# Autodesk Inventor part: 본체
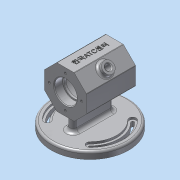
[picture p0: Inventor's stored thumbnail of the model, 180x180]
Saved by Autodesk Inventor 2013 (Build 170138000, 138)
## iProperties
Created: 2017-06
Part Number: 본체
Material: 알루미늄 6061
Document SubType Name: Modeling
Designer: Administrator
Density: 2.71 g/cm^3
Mass: 562.521 g
Surface Area: 565.55 cm^2
Volume: 207.572 cm^3
Author: Administrator
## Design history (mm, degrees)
sketch "스케치1"
  geometry: 1 further point
sketch "스케치2"
  geometry: C1 r 55 at (0, 0); 1 further point
  constraints: 1 centre point, 1 coincident
  dimensions: "d0" = 110 diameter of C1
extrude "돌출1" new body sketch "스케치2" distance "d2" = 10; taper "d3" = 0 deg
sketch "스케치3" dims "d4" = 60
  geometry: L1 (-55, 0)-(55, 0) reference; L2 (-30, 74.426)-(-12.426, 92); L3 (-12.426, 92)-(12.426, 92); L4 (12.426, 92)-(30, 74.426); L5 (30, 74.426)-(30, 49.574); L6 (30, 49.574)-(12.426, 32); L7 (12.426, 32)-(-12.426, 32); L8 (-12.426, 32)-(-30, 49.574); L9 (-30, 49.574)-(-30, 74.426); 4 further points
  constraints: 16 end point, 2 horizontal alignment, 1 coincident, 1 midpoint, 1 vertical alignment, 19 other
  dimensions: "d6" = 62 distance from line of L1 point (0, 62)
extrude "돌출2" join sketch "스케치3" stored distance "d7" = 70; taper "d8" = 0 deg
sketch "스케치4"
  geometry: L1 (-55, 0)-(55, 0) reference; C1 r 16 at (0, 62); 1 further point
  constraints: 1 centre point, 1 vertical alignment
  dimensions: "d9" = 62 distance from line of L1 C1.centre; "d10" = 32 diameter of C1
extrude "돌출3" cut sketch "스케치4" distance "d11" = 12; taper "d12" = 0 deg
sketch "스케치5"
  geometry: C1 r 16 at (0, 0) reference; C2 r 14 at (0, 0); 1 further point
  constraints: 1 centre point, 1 coincident
  dimensions: "d13" = 28 diameter of C2
extrude "돌출4" cut sketch "스케치5" distance "d15" = 3; taper "d16" = 0 deg
sketch "스케치6"
  geometry: C1 r 14 at (0, 0) reference; C2 r 25 at (0, 0); 1 further point
  constraints: 1 centre point, 1 coincident
  dimensions: "d17" = 50 diameter of C2
extrude "돌출5" cut sketch "스케치6" distance "d19" = 40; taper "d20" = 0 deg
sketch "스케치7"
  geometry: L1 (55, 0)-(-55, 0) reference; C1 r 16 at (0, -62); 2 further points
  constraints: 1 centre point, 1 midpoint, 1 vertical alignment
  dimensions: "d21" = 62 distance from line of L1 C1.centre; "d22" = 32 diameter of C1
extrude "돌출6" cut sketch "스케치7" distance "d23" = 12; taper "d24" = 0 deg
sketch "스케치8"
  geometry: C1 r 16 at (0, 0) reference; C2 r 14 at (0, 0); 1 further point
  constraints: 1 centre point, 1 coincident
  dimensions: "d25" = 28 diameter of C2
extrude "돌출7" cut sketch "스케치8" distance "d27" = 3; taper "d28" = 0 deg
fillet "모깎기1" dims "d29" = 0.3
fillet "모깎기2" dims "d30" = 3
chamfer "모따기1" distance "d31" = 1; stored, may be unused: second distance "d32" = 2, angle "d33" = 45 deg
sketch "스케치9"
  geometry: L1 (-5, 24)-(-5, -24); L2 (5, 24)-(5, -24); C1 r 55 at (0, 0) reference; A1 r 5 centre (0, 24) between (5, 24) and (-5, 24); A2 r 5 centre (0, -24) between (-5, -24) and (5, -24)
  constraints: 4 end point, 4 point on circle, 2 centre point, 2 tangent, 2 vertical alignment, 1 equal radius, 1 parallel, 1 vertical
  dimensions: "d34" = 5 radius of A1; "d36" = 48 distance of A2.centre A1.centre; "d37" = 24 distance of C1.centre A2.centre
extrude "돌출8" join sketch "스케치9" stored distance "d38" = 3; taper "d39" = 0 deg
fillet "모깎기3" dims "d40" = 5
fillet "모깎기4" dims "d41" = 1
sketch "스케치10"
  geometry: C1 r 17 at (0, 62) reference; 5 further points
  constraints: 1 vertical alignment, 5 other
  dimensions: "d42" = 23 distance of C1.centre point (0, 85); "d45" = 360 deg dimension on C1.centre point (0, 85) (derived)
hole "구멍1" sketch "스케치10" at (0, 85), (23, 62), (0, 39), (-23, 62) diameter "d47" = 3.242; stored, may be unused: countersink angle "d51" = 90 deg, drill point angle "d53" = 118 deg; dims "d48" = 8, "d49" = 4, "d50" = 2, "d52" = 10
sketch "스케치11"
  geometry: C1 r 17 at (0, -62) reference; 5 further points
  constraints: 1 vertical alignment, 5 other
  dimensions: "d54" = 23 distance of C1.centre point (0, -39); "d57" = 360 deg dimension on C1.centre point (0, -39) (derived)
hole "구멍2" sketch "스케치11" at (0, -85), (23, -62), (0, -39), (-23, -62) diameter "d59" = 3.242; stored, may be unused: countersink angle "d63" = 90 deg, drill point angle "d65" = 118 deg; dims "d60" = 8, "d61" = 4, "d62" = 2, "d64" = 10
fillet "모깎기5" dims "d66" = 3
sketch "스케치12"
  geometry: L1 (10, -24)-(10, 24) reference; L2 (-30.406, -30.406)-(30.406, 30.406); L3 (0, 0)-(-52, 0); A1 r 5 centre (-30.406, -30.406) between (-33.941, -33.941) and (-26.87, -26.87); A2 r 2 centre (-30.406, -30.406) between (-31.82, -31.82) and (-28.991, -28.991); A3 r 5 centre (-30.406, 30.406) between (-26.87, 26.87) and (-33.941, 33.941); A4 r 2 centre (-30.406, 30.406) between (-28.991, 28.991) and (-31.82, 31.82); A5 r 5 centre (30.406, 30.406) between (33.941, 33.941) and (26.87, 26.87); A6 r 2 centre (30.406, 30.406) between (31.82, 31.82) and (28.991, 28.991); A7 r 5 centre (30.406, -30.406) between (26.87, -26.87) and (33.941, -33.941); A8 r 2 centre (30.406, -30.406) between (28.991, -28.991) and (31.82, -31.82); A9 r 48 centre (0, 0) between (33.941, -33.941) and (33.941, 33.941); A10 r 48 centre (0, 0) between (-33.941, 33.941) and (-33.941, -33.941); A11 r 43 centre (0, 0) between (26.67, -33.73) and (26.67, 33.73); A12 r 43 centre (0, 0) between (-26.67, 33.73) and (-26.67, -33.73); A13 r 38 centre (0, 0) between (26.87, -26.87) and (26.87, 26.87); A14 r 38 centre (0, 0) between (-26.87, 26.87) and (-26.87, -26.87); A15 r 45 centre (0, 0) between (31.82, -31.82) and (31.82, 31.82); A16 r 45 centre (0, 0) between (-31.82, 31.82) and (-31.82, -31.82); A17 r 41 centre (0, 0) between (28.991, -28.991) and (28.991, 28.991); A18 r 41 centre (0, 0) between (-28.991, 28.991) and (-28.991, -28.991); 1 further point
  constraints: 45 point on circle, 18 centre point, 10 equal radius, 9 coincident, 4 end point, 4 point on line, 3 horizontal alignment, 2 vertical alignment, 1 perpendicular, 1 other
  dimensions: "d71" = 45 deg angle of L3 L2; "d72" = 38 radius of A14; "d74" = 43 radius of A12; "d75" = 48 radius of A10; "d76" = 4 diameter of A2; "d77" = 45 radius of A16
extrude "돌출9" cut sketch "스케치12" distance "d78" = 3; taper "d79" = 0 deg
sketch "스케치13"
  geometry: A1 r 41 centre (0, 0) between (-28.991, 28.991) and (-28.991, -28.991) reference; A2 r 2 centre (-30.406, 30.406) between (-28.991, 28.991) and (-31.82, 31.82) reference; A3 r 45 centre (0, 0) between (-31.82, 31.82) and (-31.82, -31.82) reference; A4 r 2 centre (-30.406, -30.406) between (-31.82, -31.82) and (-28.991, -28.991) reference; A5 r 45 centre (0, 0) between (31.82, -31.82) and (31.82, 31.82) reference; A6 r 2 centre (30.406, 30.406) between (31.82, 31.82) and (28.991, 28.991) reference; A7 r 41 centre (0, 0) between (28.991, -28.991) and (28.991, 28.991) reference; A8 r 2 centre (30.406, -30.406) between (28.991, -28.991) and (31.82, -31.82) reference
extrude "돌출10" cut sketch "스케치13" stored distance "d80" = 3; taper "d81" = 0 deg
node "작업 평면1"
sketch "스케치14"
  geometry: L1 (8.975, -59.31)-(8.975, -10.69); L2 (8.975, -10.69)-(15.635, -10.69); L3 (15.635, -10.69)-(15.635, -59.31); L4 (15.635, -59.31)-(8.975, -59.31); L5 (12.305, -59.31)-(12.305, -10.69); L6 (8.975, -35)-(15.635, -35); L7 (-17.695, -70)-(-17.695, 0) reference; L8 (-0.707, -70)-(-17.695, -70) reference; 1 further point
  constraints: 4 end point, 4 midpoint, 1 perpendicular, 2 other
  dimensions: "d83" = 30 distance between parallel lines of L7 L5; "d84" = 35 distance between parallel lines of L8 L6
feature "엠보싱1" sketch "스케치14" dims "d85" = 0.5, "d86" = 0
sketch "스케치15"
  geometry: L1 (0, 70)-(24.024, 70) reference; C1 r 8 at (12.012, 35); 2 further points
  constraints: 1 centre point, 1 horizontal alignment, 1 midpoint, 1 vertical alignment
  dimensions: "d87" = 16 diameter of C1
extrude "돌출11" join sketch "스케치15" distance "d90" = 7; taper "d91" = 0 deg
fillet "모깎기6" dims "d92" = 3
sketch "스케치16"
  geometry: C1 r 8 at (0, 0) reference; C2 r 4 at (0, 0); 1 further point
  constraints: 1 centre point, 1 coincident
  dimensions: "d93" = 8 diameter of C2
extrude "돌출12" cut sketch "스케치16" stored distance "d95" = 7; taper "d96" = 0 deg
chamfer "모따기2" distance "d97" = 1; stored, may be unused: second distance "d98" = 2, angle "d99" = 45 deg
node "솔리드1"
node "투영된 루프1"
other parameters: "d67" = 76, "d69" = 86, "d70" = 96, "d82" = 8.5
